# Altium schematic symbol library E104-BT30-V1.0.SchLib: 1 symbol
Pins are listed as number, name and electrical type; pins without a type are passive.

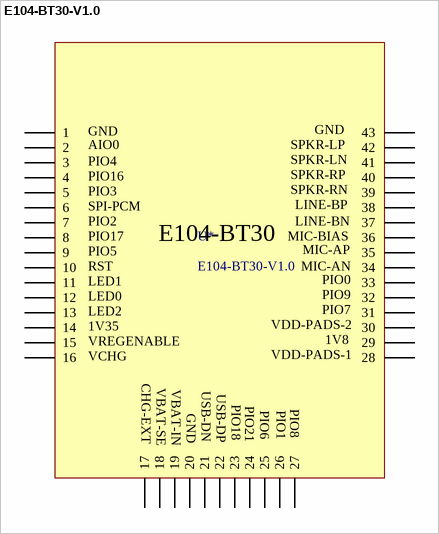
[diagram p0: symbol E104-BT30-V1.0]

## E104-BT30-V1.0
designator U*
footprint E104-BT30-V1.0 (P43)
pins: 1, 2, 3, 4, 5, 6, 7, 8, 9, 10, 11, 12, 13, 14, 15, 16, 17, 18, 19, 20, 21, 22, 23, 24, 25, 26, 27, 28, 29, 30, 31, 32, 33, 34, 35, 36, 37, 38, 39, 40, 41, 42, 43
